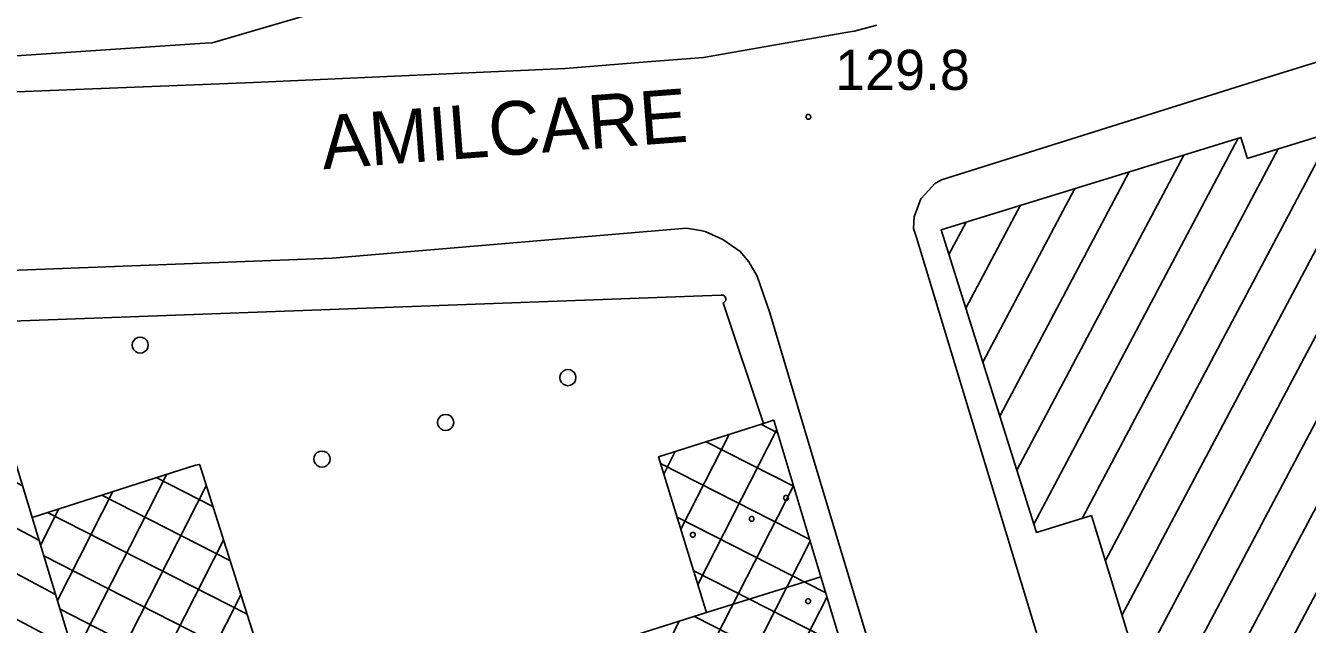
# Model space of a CAD drawing. Extents: x 513373 to 514978, y 5038576 to 5040180.
# Drawn here: x 513597.32 to 513645.09, y 5038694.11 to 5038716.44 of the extents above; entities that cross this region are included whole.
import ezdxf

# ---------------------------------------------------------------- set-up
doc = ezdxf.new("R2010")
doc.units = 0
for name, color, linetype in [('2010300', 7, 'Continuous'), ('B1211', 7, 'Continuous'), ('C1131', 7, 'Continuous'), ('C12211', 7, 'Continuous'), ('C1228', 7, 'Continuous'), ('CAMP_C12211', 7, 'Continuous'), ('CAMP_C1228', 7, 'Continuous'), ('Default', 7, 'Continuous'), ('F12107', 7, 'Continuous'), ('F12131', 7, 'Continuous'), ('F12132', 7, 'Continuous'), ('G4315', 7, 'Continuous'), ('TOP500', 7, 'Continuous'), ('TOP920', 7, 'Continuous')]:
    doc.layers.add(name, color=color, linetype=linetype)

# ---------------------------------------------------------------- blocks, each defined once
blk = doc.blocks.new('CAMP_2C1236C1')
at = {"layer": 'CAMP_C12211'}
for p, q in [((-31.743, -9.383), (-17.651, 17.232)), ((-32.365, -7.353), (-19.679, 16.607)), ((-32.987, -5.322), (-21.708, 15.982)), ((-33.61, -3.291), (-23.736, 15.357)), ((-36.897, 0.117), (-29.28, 14.502)), ((-34.232, -1.261), (-25.764, 14.732)), ((-37.529, 2.129), (-31.309, 13.877)), ((-35.088, 0.328), (-27.792, 14.107)), ((-38.161, 4.14), (-33.337, 13.252)), ((-38.794, 6.151), (-35.365, 12.627)), ((-39.426, 8.163), (-37.393, 12.002)), ((-40.058, 10.174), (-39.421, 11.378)), ((-31.121, -11.414), (-23.978, 2.077))]:
    blk.add_line(p, q, dxfattribs=at)
blk = doc.blocks.new('CAMP_D0075765')
at = {"layer": 'CAMP_C1228'}
for p, q in [((9.463, 3.83), (12.397, 9.588)), ((12.43, 9.48), (11.803, 9.8)), ((8.828, 5.888), (10.63, 9.424)), ((13.03, 7.491), (9.773, 9.15)), ((8.193, 7.945), (8.619, 8.781)), ((13.629, 5.502), (8.074, 8.333)), ((-13.783, 1.159), (-10.328, 7.941)), ((-8.617, 6.736), (-10.728, 7.812)), ((-14.413, 3.227), (-12.34, 7.294)), ((-13.153, -0.909), (-8.863, 7.511)), ((6.786, -4.73), (13.023, 7.512)), ((-7.98, 4.728), (-12.755, 7.161)), ((-15.043, 5.294), (-14.353, 6.648)), ((-7.343, 2.72), (-14.782, 6.51)), ((14.229, 3.513), (8.69, 6.335)), ((-12.523, -2.976), (-8.217, 5.475)), ((8.784, -4.112), (13.649, 5.437)), ((-6.706, 0.712), (-14.922, 4.898)), ((14.829, 1.524), (9.306, 4.338)), ((-11.893, -5.044), (-7.571, 3.439)), ((10.782, -3.495), (14.275, 3.361)), ((-6.068, -1.296), (-14.315, 2.906)), ((4.787, -5.347), (8.762, 2.453)), ((15.429, -0.465), (9.341, 2.637)), ((15.319, -2.093), (7.305, 1.99)), ((2.789, -5.964), (6.753, 1.815)), ((-11.263, -7.112), (-6.925, 1.403)), ((0.791, -6.582), (4.745, 1.178)), ((13.262, -2.728), (5.27, 1.344)), ((12.78, -2.877), (14.901, 1.286)), ((-5.431, -3.305), (-13.708, 0.913)), ((-1.207, -7.199), (2.737, 0.54)), ((11.205, -3.364), (3.234, 0.698)), ((9.149, -3.999), (1.198, 0.052)), ((-3.205, -7.816), (0.728, -0.097)), ((-10.633, -9.179), (-6.279, -0.633)), ((-2.086, -2.317), (-1.28, -0.735)), ((7.092, -4.635), (-0.838, -0.595)), ((14.778, -2.26), (15.527, -0.79)), ((-1.135, -7.177), (-13.101, -1.08)), ((5.035, -5.27), (-2.343, -1.511)), ((-9.199, -9.668), (-5.633, -2.669)), ((-3.192, -7.812), (-12.494, -3.073)), ((2.978, -5.906), (-1.704, -3.52)), ((-5.203, -8.434), (-2.956, -4.023)), ((0.922, -6.541), (-3.612, -4.232)), ((-7.201, -9.051), (-4.964, -4.661)), ((-5.249, -8.448), (-11.886, -5.066)), ((-7.305, -9.083), (-11.279, -7.059)), ((-9.362, -9.719), (-10.672, -9.052))]:
    blk.add_line(p, q, dxfattribs=at)
blk = doc.blocks.new('CAMP_AE7E8461')
at = {"layer": 'CAMP_C12211'}
for p, q in [((7.76, 8.621), (6.302, 9.393)), ((8.377, 6.597), (4.261, 8.776)), ((8.993, 4.573), (2.219, 8.16)), ((9.61, 2.55), (0.179, 7.543)), ((10.226, 0.526), (-1.863, 6.927)), ((10.843, -1.498), (-3.904, 6.31)), ((11.46, -3.522), (-5.945, 5.694)), ((10.188, -4.546), (-7.987, 5.077)), ((8.146, -5.162), (-10.028, 4.461)), ((6.105, -5.778), (-11.646, 3.62)), ((4.064, -6.395), (-11.036, 1.6)), ((2.023, -7.012), (-10.426, -0.42)), ((-0.018, -7.628), (-9.816, -2.441)), ((-2.06, -8.245), (-9.205, -4.461)), ((-4.101, -8.861), (-8.595, -6.481)), ((-6.142, -9.478), (-7.985, -8.502))]:
    blk.add_line(p, q, dxfattribs=at)
blk = doc.blocks.new('08020400')
at = {"layer": 'Default'}
for p, q in [((-0.086, 0.028), (-0.09, 0)), ((-0.09, 0), (-0.086, -0.028)), ((-0.073, 0.053), (-0.086, 0.028)), ((-0.053, 0.073), (-0.073, 0.053)), ((-0.028, 0.086), (-0.053, 0.073)), ((0, 0.09), (-0.028, 0.086)), ((0.028, 0.086), (0, 0.09)), ((0.053, 0.073), (0.028, 0.086)), ((0.073, 0.053), (0.053, 0.073)), ((0.086, 0.028), (0.073, 0.053)), ((0.09, 0), (0.086, 0.028)), ((0.086, -0.028), (0.09, 0)), ((-0.086, -0.028), (-0.073, -0.053)), ((-0.073, -0.053), (-0.053, -0.073)), ((-0.053, -0.073), (-0.028, -0.086)), ((-0.028, -0.086), (0, -0.09)), ((0, -0.09), (0.028, -0.086)), ((0.028, -0.086), (0.053, -0.073)), ((0.053, -0.073), (0.073, -0.053)), ((0.073, -0.053), (0.086, -0.028))]:
    blk.add_line(p, q, dxfattribs=at)
blk = doc.blocks.new('NSIMB25')
at = {"layer": 'Default'}
for p, q in [((-0.086, 0.028), (-0.09, 0)), ((-0.09, 0), (-0.086, -0.028)), ((-0.073, 0.053), (-0.086, 0.028)), ((-0.053, 0.073), (-0.073, 0.053)), ((-0.028, 0.086), (-0.053, 0.073)), ((0, 0.09), (-0.028, 0.086)), ((0.028, 0.086), (0, 0.09)), ((0.053, 0.073), (0.028, 0.086)), ((0.073, 0.053), (0.053, 0.073)), ((0.086, 0.028), (0.073, 0.053)), ((0.09, 0), (0.086, 0.028)), ((0.086, -0.028), (0.09, 0)), ((-0.086, -0.028), (-0.073, -0.053)), ((-0.073, -0.053), (-0.053, -0.073)), ((-0.053, -0.073), (-0.028, -0.086)), ((-0.028, -0.086), (0, -0.09)), ((0, -0.09), (0.028, -0.086)), ((0.028, -0.086), (0.053, -0.073)), ((0.053, -0.073), (0.073, -0.053)), ((0.073, -0.053), (0.086, -0.028))]:
    blk.add_line(p, q, dxfattribs=at)
blk = doc.blocks.new('05010100')
at = {"layer": 'Default'}
for p, q in [((-0.143, 0.046), (-0.15, 0)), ((-0.15, 0), (-0.143, -0.046)), ((-0.121, 0.088), (-0.143, 0.046)), ((-0.088, 0.121), (-0.121, 0.088)), ((-0.046, 0.143), (-0.088, 0.121)), ((0, 0.15), (-0.046, 0.143)), ((0.046, 0.143), (0, 0.15)), ((0.088, 0.121), (0.046, 0.143)), ((0.121, 0.088), (0.088, 0.121)), ((0.143, 0.046), (0.121, 0.088)), ((0.15, 0), (0.143, 0.046)), ((0.143, -0.046), (0.15, 0)), ((-0.143, -0.046), (-0.121, -0.088)), ((-0.121, -0.088), (-0.088, -0.121)), ((-0.088, -0.121), (-0.046, -0.143)), ((-0.046, -0.143), (0, -0.15)), ((0, -0.15), (0.046, -0.143)), ((0.046, -0.143), (0.088, -0.121)), ((0.088, -0.121), (0.121, -0.088)), ((0.121, -0.088), (0.143, -0.046))]:
    blk.add_line(p, q, dxfattribs=at)
blk = doc.blocks.new('A$C3704598A')
at = {"layer": '2010300'}
blk.add_lwpolyline([(250.187, -673.747), (220.701, -674.825), (220.657, -674.837), (220.622, -674.86), (220.592, -674.895), (220.576, -674.93), (220.569, -674.969)], dxfattribs=at)
at = {"layer": 'B1211'}
for points in [[(173.727, -671.63), (194.458, -666.341), (195.377, -666.107), (205.007, -665.815), (205.917, -665.787), (205.948, -665.78), (205.978, -665.765), (206.011, -665.737), (206.034, -665.702), (206.046, -665.662), (206.047, -665.624), (211.749, -665.462), (211.753, -665.508), (211.753, -665.514), (211.771, -665.557), (211.792, -665.583), (211.819, -665.604), (211.849, -665.619), (211.891, -665.626), (230.945, -664.352), (231.219, -664.334), (235.826, -662.991)], [(256.002, -663.682), (255.149, -663.9), (254.839, -663.954), (249.54, -664.885), (247.444, -665.051), (244.386, -665.293), (232.769, -665.818), (213.489, -666.579), (204.982, -666.923), (204.832, -666.94), (204.516, -667.138), (203.533, -667.753), (203.346, -667.79), (202.779, -667.822), (197.934, -668.094), (196.016, -668.259), (194.009, -668.478), (192.633, -668.792), (192.434, -668.841), (178.888, -672.206), (176.406, -672.89)], [(314.878, -654.761), (269.808, -668.647), (269.785, -668.574), (269.568, -667.868), (268.566, -668.177), (258.4, -671.309), (261.926, -682.527), (261.949, -682.598), (262.994, -682.277), (263.997, -681.97), (271.91, -707.801), (270.707, -708.17), (272.084, -712.665)], [(283.252, -756.933), (264.211, -693.769), (259.814, -679.302), (257.474, -671.601), (257.45, -671.522), (257.371, -671.263), (257.393, -670.826), (257.636, -670.153), (257.934, -669.828), (258.151, -669.592), (258.407, -669.448), (270.456, -665.66), (287.698, -660.31)], [(255.736, -690.288), (253.915, -684.25), (252.154, -678.411), (252.108, -678.425), (251.776, -678.532), (250.272, -674.033), (250.302, -674.019), (250.335, -673.991), (250.358, -673.956), (250.371, -673.916), (250.371, -673.87), (250.358, -673.83), (250.336, -673.796), (250.306, -673.768), (250.275, -673.753), (250.23, -673.743), (250.187, -673.747), (220.701, -674.825)], [(220.105, -672.964), (235.7, -672.365), (248.909, -671.256), (249.421, -671.343), (249.6, -671.374), (250.254, -671.679), (250.907, -672.115), (251.222, -672.511), (251.536, -673.038), (251.673, -673.434), (252.012, -674.41), (253.398, -679.084), (256.672, -689.963)]]:
    blk.add_lwpolyline(points, dxfattribs=at)
at = {"layer": 'C1131'}
blk.add_lwpolyline([(272.084, -712.665), (270.707, -708.17), (271.91, -707.801), (263.997, -681.97), (262.994, -682.277), (261.949, -682.598), (261.926, -682.527), (258.4, -671.309), (268.566, -668.177), (269.568, -667.868), (269.785, -668.574), (269.808, -668.647), (314.878, -654.761)], dxfattribs=at)
for points in [[(208.476, -697.287), (208.214, -697.366), (208.194, -697.3), (207.59, -695.3), (205.129, -687.152), (204.031, -683.517), (210.127, -681.676), (213.684, -680.602), (215.397, -680.085), (217.397, -679.48), (221.642, -678.198), (222.193, -678.032), (223.197, -677.729), (224.484, -681.955), (224.51, -682.039), (227.413, -691.567), (226.409, -691.87), (222.271, -693.12), (216.656, -694.816)], [(253.915, -684.25), (252.914, -684.564), (249.655, -685.587), (249.631, -685.509), (247.864, -679.783), (251.155, -678.73), (251.776, -678.532), (252.108, -678.425), (252.154, -678.411)], [(230.797, -680.201), (234.844, -692.956), (234.87, -693.036), (235.889, -696.34), (235.912, -696.413), (229.494, -698.396), (229.471, -698.323), (229.393, -698.065), (228.419, -694.868), (227.756, -692.691), (227.413, -691.567), (224.51, -682.039), (229.748, -680.358), (230.605, -680.082), (230.752, -680.059), (230.772, -680.122)], [(255.736, -690.288), (255.68, -690.305), (255.429, -690.383), (255.325, -690.415), (254.427, -690.692), (251.724, -691.528), (250.722, -691.837), (242.358, -694.422), (241.357, -694.731), (239.216, -695.392), (239.194, -695.319), (238.194, -691.981), (237.398, -689.477), (249.655, -685.587), (252.914, -684.564), (253.915, -684.25)]]:
    blk.add_lwpolyline(points, close=True, dxfattribs=at)
at = {"layer": 'C12211'}
blk.add_lwpolyline([(272.084, -712.665), (270.707, -708.17), (271.91, -707.801), (263.997, -681.97), (262.994, -682.277), (261.949, -682.598), (261.926, -682.527), (258.4, -671.309), (268.566, -668.177), (269.568, -667.868), (269.785, -668.574), (269.808, -668.647), (314.878, -654.761)], dxfattribs=at)
blk.add_lwpolyline([(208.476, -697.287), (208.214, -697.366), (208.194, -697.3), (207.59, -695.3), (205.129, -687.152), (204.031, -683.517), (210.127, -681.676), (213.684, -680.602), (215.397, -680.085), (217.397, -679.48), (221.642, -678.198), (222.193, -678.032), (223.197, -677.729), (224.484, -681.955), (224.51, -682.039), (227.413, -691.567), (226.409, -691.87), (222.271, -693.12), (216.656, -694.816)], close=True, dxfattribs=at)
at = {"layer": 'C1228'}
for points in [[(227.413, -691.567), (224.51, -682.039), (229.748, -680.358), (230.605, -680.082), (230.752, -680.059), (230.772, -680.122), (230.797, -680.201), (234.844, -692.956)], [(237.398, -689.477), (249.655, -685.587), (249.631, -685.509), (247.864, -679.783), (251.155, -678.73), (251.776, -678.532), (252.108, -678.425), (252.154, -678.411), (253.915, -684.25), (255.736, -690.288)]]:
    blk.add_lwpolyline(points, dxfattribs=at)
at = {"layer": 'CAMP_C12211'}
for name, p in [('CAMP_2C1236C1', (298.747, -682.401)), ('CAMP_AE7E8461', (215.775, -687.46))]:
    blk.add_blockref(name, p, dxfattribs=at)
at = {"layer": 'CAMP_C1228'}
blk.add_blockref('CAMP_D0075765', (239.867, -688.365), dxfattribs=at)
at = {"layer": 'F12107'}
blk.add_blockref('08020400', (253.447, -667.096), dxfattribs=at)
at = {"layer": 'F12131'}
blk.add_blockref('NSIMB25', (251.334, -682.088), dxfattribs=at)
at = {"layer": 'F12132'}
for p in [(252.613, -681.31), (249.143, -682.683), (253.441, -685.16)]:
    blk.add_blockref('NSIMB25', p, dxfattribs=at)
at = {"layer": 'G4315', "xscale": 2, "yscale": 2}
for p in [(228.541, -675.612), (244.483, -676.825), (239.927, -678.493), (235.318, -679.86)]:
    blk.add_blockref('05010100', p, dxfattribs=at)
at = {"layer": 'TOP500'}
blk.add_text('AMILCARE', height=2, rotation=4.3403, dxfattribs=at).set_placement((235.367, -669.057))
at = {"layer": 'TOP920'}
blk.add_text('129.8', height=1.5, dxfattribs=at).set_placement((254.447, -666.096))

msp = doc.modelspace()

# ---------------------------------------------------------------- block references
at = {"layer": 'Default'}
msp.add_blockref('A$C3704598A', (513373.046, 5039380.14), dxfattribs=at)

doc.saveas('drawing.dxf')
